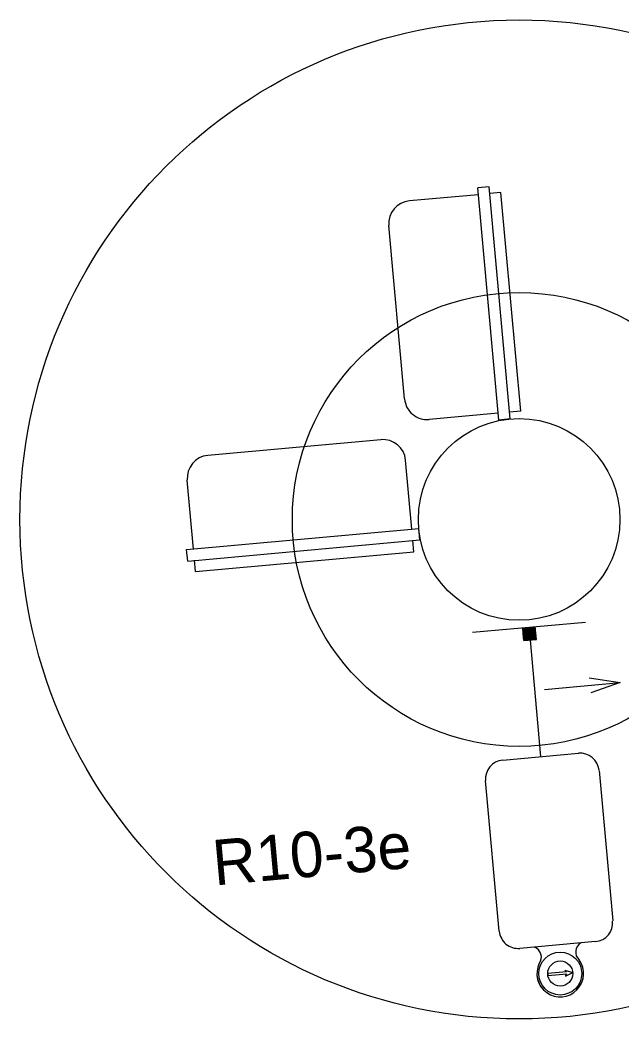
# Model space of a CAD drawing. Extents: x 1277218 to 1279252, y 196860 to 197529.
# Drawn here: x 1278964.8 to 1279025.6, y 197191.1 to 197292.1 of the extents above; entities that cross this region are included whole.
import ezdxf

# ---------------------------------------------------------------- set-up
doc = ezdxf.new("R2010")
doc.units = 0
doc.layers.add('S_EDGE_PAVEMENT', color=7, linetype='Continuous')

msp = doc.modelspace()

# ---------------------------------------------------------------- linework, layer by layer
at = {"layer": 'S_EDGE_PAVEMENT'}
for p, q in [((1279012.26, 197275.26), (1279011.12, 197275.15)), ((1279014.39, 197251.77), (1279012.26, 197275.26)), ((1279011.18, 197274.45), (1279004.2, 197273.82)), ((1279013.25, 197251.66), (1279011.12, 197275.15)), ((1279013.47, 197274.66), (1279012.33, 197274.56)), ((1279015.47, 197252.57), (1279013.47, 197274.66)), ((1279003.71, 197253.81), (1279002.12, 197271.33)), ((1279013.19, 197252.36), (1279006.2, 197251.73)), ((1279015.47, 197252.57), (1279014.33, 197252.46)), ((1279014.39, 197251.77), (1279013.25, 197251.66)), ((1278983.81, 197248.1), (1279001.33, 197249.69)), ((1279004.46, 197240.62), (1279003.82, 197247.61)), ((1278982.36, 197238.62), (1278981.73, 197245.6)), ((1278981.66, 197238.56), (1279005.15, 197240.69)), ((1279005.26, 197239.54), (1279005.15, 197240.69)), ((1278981.77, 197237.41), (1279005.26, 197239.54)), ((1279004.66, 197238.34), (1279004.56, 197239.48)), ((1278981.77, 197237.41), (1278981.66, 197238.56)), ((1278982.57, 197236.34), (1279004.66, 197238.34)), ((1278982.57, 197236.34), (1278982.46, 197237.48)), ((1279022.02, 197231.2), (1279010.59, 197230.17)), ((1279015.75, 197229.67), (1279016.63, 197230.72)), ((1279015.75, 197229.69), (1279016.6, 197230.71)), ((1279015.75, 197229.71), (1279016.58, 197230.71)), ((1279015.75, 197229.73), (1279016.56, 197230.71)), ((1279015.75, 197229.76), (1279016.54, 197230.71)), ((1279015.76, 197229.54), (1279016.75, 197230.73)), ((1279015.76, 197229.56), (1279016.73, 197230.73)), ((1279015.76, 197229.58), (1279016.71, 197230.72)), ((1279015.76, 197229.61), (1279016.69, 197230.72)), ((1279015.76, 197229.63), (1279016.67, 197230.72)), ((1279015.76, 197229.65), (1279016.65, 197230.72)), ((1279015.77, 197229.43), (1279016.86, 197230.74)), ((1279015.77, 197229.45), (1279016.84, 197230.74)), ((1279015.77, 197229.48), (1279016.82, 197230.73)), ((1279015.77, 197229.5), (1279016.8, 197230.73)), ((1279015.77, 197229.52), (1279016.78, 197230.73)), ((1279015.78, 197229.37), (1279016.93, 197230.74)), ((1279015.78, 197229.39), (1279016.91, 197230.74)), ((1279015.78, 197229.41), (1279016.88, 197230.74)), ((1279015.79, 197229.36), (1279016.94, 197230.73)), ((1279015.82, 197229.36), (1279016.94, 197230.71)), ((1279017.05, 197229.47), (1279016.94, 197230.74)), ((1279015.67, 197230.55), (1279015.74, 197230.64)), ((1279015.78, 197229.36), (1279015.67, 197230.63)), ((1279015.67, 197230.58), (1279015.72, 197230.63)), ((1279015.67, 197230.6), (1279015.7, 197230.63)), ((1279015.67, 197230.62), (1279015.68, 197230.63)), ((1279015.68, 197230.42), (1279015.87, 197230.65)), ((1279015.68, 197230.45), (1279015.85, 197230.65)), ((1279015.68, 197230.47), (1279015.83, 197230.64)), ((1279015.68, 197230.49), (1279015.81, 197230.64)), ((1279015.68, 197230.51), (1279015.78, 197230.64)), ((1279015.68, 197230.53), (1279015.76, 197230.64)), ((1279015.69, 197230.32), (1279015.98, 197230.66)), ((1279015.69, 197230.34), (1279015.96, 197230.66)), ((1279015.69, 197230.36), (1279015.94, 197230.65)), ((1279015.69, 197230.38), (1279015.91, 197230.65)), ((1279015.69, 197230.4), (1279015.89, 197230.65)), ((1279015.7, 197230.21), (1279016.09, 197230.67)), ((1279015.7, 197230.23), (1279016.07, 197230.67)), ((1279015.7, 197230.25), (1279016.04, 197230.66)), ((1279015.7, 197230.27), (1279016.02, 197230.66)), ((1279015.7, 197230.3), (1279016, 197230.66)), ((1279015.71, 197230.1), (1279016.19, 197230.68)), ((1279015.71, 197230.12), (1279016.17, 197230.68)), ((1279015.71, 197230.14), (1279016.15, 197230.67)), ((1279015.71, 197230.17), (1279016.13, 197230.67)), ((1279015.71, 197230.19), (1279016.11, 197230.67)), ((1279015.72, 197229.99), (1279016.3, 197230.69)), ((1279015.72, 197230.01), (1279016.28, 197230.68)), ((1279015.72, 197230.04), (1279016.26, 197230.68)), ((1279015.72, 197230.06), (1279016.24, 197230.68)), ((1279015.72, 197230.08), (1279016.22, 197230.68)), ((1279015.73, 197229.89), (1279016.41, 197230.7)), ((1279015.73, 197229.91), (1279016.39, 197230.69)), ((1279015.73, 197229.93), (1279016.37, 197230.69)), ((1279015.73, 197229.95), (1279016.35, 197230.69)), ((1279015.73, 197229.97), (1279016.32, 197230.69)), ((1279015.74, 197229.78), (1279016.52, 197230.71)), ((1279015.74, 197229.8), (1279016.5, 197230.7)), ((1279015.74, 197229.82), (1279016.47, 197230.7)), ((1279015.74, 197229.84), (1279016.45, 197230.7)), ((1279015.74, 197229.86), (1279016.43, 197230.7)), ((1279015.84, 197229.36), (1279016.94, 197230.69)), ((1279015.86, 197229.37), (1279016.94, 197230.67)), ((1279015.88, 197229.37), (1279016.95, 197230.65)), ((1279015.9, 197229.37), (1279016.95, 197230.62)), ((1279015.92, 197229.37), (1279016.95, 197230.6)), ((1279015.94, 197229.37), (1279016.95, 197230.58)), ((1279015.97, 197229.38), (1279016.95, 197230.56)), ((1279015.99, 197229.38), (1279016.95, 197230.54)), ((1279016.01, 197229.38), (1279016.96, 197230.52)), ((1279016.03, 197229.38), (1279016.96, 197230.49)), ((1279016.05, 197229.38), (1279016.96, 197230.47)), ((1279016.07, 197229.39), (1279016.96, 197230.45)), ((1279016.1, 197229.39), (1279016.96, 197230.43)), ((1279016.12, 197229.39), (1279016.97, 197230.41)), ((1279016.14, 197229.39), (1279016.97, 197230.39)), ((1279016.16, 197229.39), (1279016.97, 197230.37)), ((1279016.18, 197229.4), (1279016.97, 197230.34)), ((1279016.2, 197229.4), (1279016.97, 197230.32)), ((1279016.22, 197229.4), (1279016.98, 197230.3)), ((1279016.25, 197229.4), (1279016.98, 197230.28)), ((1279016.27, 197229.4), (1279016.98, 197230.26)), ((1279016.29, 197229.41), (1279016.98, 197230.24)), ((1279016.31, 197229.41), (1279016.98, 197230.21)), ((1279016.33, 197229.41), (1279016.99, 197230.19)), ((1279016.35, 197229.41), (1279016.99, 197230.17)), ((1279016.38, 197229.41), (1279016.99, 197230.15)), ((1279016.4, 197229.42), (1279016.99, 197230.13)), ((1279016.42, 197229.42), (1279016.99, 197230.11)), ((1279016.44, 197229.42), (1279017, 197230.09)), ((1279016.46, 197229.42), (1279017, 197230.06)), ((1279016.48, 197229.42), (1279017, 197230.04)), ((1279016.5, 197229.42), (1279017, 197230.02)), ((1279016.53, 197229.43), (1279017, 197230)), ((1279016.55, 197229.43), (1279017.01, 197229.98)), ((1279016.57, 197229.43), (1279017.01, 197229.96)), ((1279016.59, 197229.43), (1279017.01, 197229.93)), ((1279016.61, 197229.43), (1279017.01, 197229.91)), ((1279016.63, 197229.44), (1279017.01, 197229.89)), ((1279016.66, 197229.44), (1279017.02, 197229.87)), ((1279016.68, 197229.44), (1279017.02, 197229.85)), ((1279016.7, 197229.44), (1279017.02, 197229.83)), ((1279016.72, 197229.44), (1279017.02, 197229.81)), ((1279016.74, 197229.45), (1279017.02, 197229.78)), ((1279016.76, 197229.45), (1279017.03, 197229.76)), ((1279016.79, 197229.45), (1279017.03, 197229.74)), ((1279016.81, 197229.45), (1279017.03, 197229.72)), ((1279015.78, 197229.36), (1279017.05, 197229.47)), ((1279016.42, 197229.42), (1279017.48, 197217.63)), ((1279016.83, 197229.45), (1279017.03, 197229.7)), ((1279016.85, 197229.46), (1279017.03, 197229.68)), ((1279016.87, 197229.46), (1279017.03, 197229.65)), ((1279016.89, 197229.46), (1279017.04, 197229.63)), ((1279016.91, 197229.46), (1279017.04, 197229.61)), ((1279016.94, 197229.46), (1279017.04, 197229.59)), ((1279016.96, 197229.47), (1279017.04, 197229.57)), ((1279016.98, 197229.47), (1279017.04, 197229.55)), ((1279017, 197229.47), (1279017.05, 197229.53)), ((1279017.02, 197229.47), (1279017.05, 197229.5)), ((1279017.04, 197229.47), (1279017.05, 197229.48)), ((1279017.86, 197224.43), (1279025.53, 197225.12)), ((1279013.65, 197217.28), (1279021.32, 197217.98)), ((1279023.4, 197216.24), (1279024.78, 197201.01)), ((1279013.3, 197199.97), (1279011.92, 197215.2)), ((1279023.04, 197198.93), (1279015.38, 197198.23)), ((1279020.11, 197195.86), (1279018.2, 197195.69)), ((1279018.2, 197195.69), (1279018.22, 197195.46)), ((1279020.13, 197195.63), (1279018.22, 197195.46)), ((1279019.94, 197196.04), (1279020.74, 197195.8)), ((1279020.11, 197195.86), (1279019.94, 197196.04)), ((1279020, 197195.43), (1279020.74, 197195.8)), ((1279020, 197195.43), (1279020.13, 197195.63))]:
    msp.add_line(p, q, dxfattribs=at)
msp.add_lwpolyline([(1279022.41, 197225.61), (1279025.53, 197225.12), (1279022.55, 197224.08)], dxfattribs=at)
for centre, radius in [((1279015.31, 197241.61), 50.51), ((1279015.31, 197241.61), 22.95), ((1279015.31, 197241.61), 10.2), ((1279019.47, 197195.69), 2.17), ((1279019.47, 197195.69), 1.27)]:
    msp.add_circle(centre, radius, dxfattribs=at)
for centre, radius, start, end in [((1279004.41, 197271.54), 2.29, 95.1779, 185.1779), ((1279005.99, 197254.01), 2.29, 185.1779, 275.1779), ((1279001.54, 197247.4), 2.29, 5.1779, 95.1779), ((1278984.01, 197245.81), 2.29, 95.1779, 185.1779), ((1279021.49, 197216.07), 1.91, 5.1779, 95.1779), ((1279013.82, 197215.38), 1.91, 95.1779, 185.1779), ((1279022.87, 197200.83), 1.91, 275.1779, 5.1779), ((1279015.2, 197200.14), 1.91, 185.1779, 275.1779), ((1279022.1, 197197.87), 1.07, 120.3735, 226.9807), ((1279016.49, 197197.36), 1.07, 323.3751, 69.9823), ((1279019.47, 197195.69), 2.36, 153.9181, 36.4377), ((1279019.47, 197195.69), 2.36, 153.9181, 232.6712), ((1279019.47, 197195.69), 2.36, 317.6845, 36.4377)]:
    msp.add_arc(centre, radius, start, end, dxfattribs=at)

# ---------------------------------------------------------------- texts
msp.add_text('R10-3e', height=4.59, rotation=5.1779, dxfattribs=at).set_placement((1278984.5, 197204.59))

doc.saveas('drawing.dxf')
